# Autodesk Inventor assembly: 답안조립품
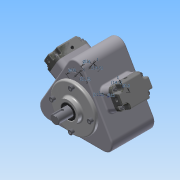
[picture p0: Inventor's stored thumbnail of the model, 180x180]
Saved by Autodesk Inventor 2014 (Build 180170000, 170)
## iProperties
Created: 2015-06
Part Number: 답안조립품
Document SubType Name: Assembly
Designer: Administrator
Mass: 5776.4 g
Surface Area: 2414.93 cm^2
Volume: 1564.62 cm^3
Density: 3.69189 g/cm^3
Author: Administrator
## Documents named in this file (20)
- C:\Documents and Settings\MYHOME\바탕 화면\350605V1053\답안조립품.iam
- C:\Documents and Settings\MYHOME\바탕 화면\350605V1053\본체.ipt
- C:\Documents and Settings\MYHOME\바탕 화면\350605V1053\부시.ipt
- C:\Documents and Settings\MYHOME\바탕 화면\350605V1053\편심축.ipt
- C:\Documents and Settings\MYHOME\바탕 화면\350605V1053\베어링 NA 4904.ipt
- 베어링 NA 4904.ipt
- C:\Documents and Settings\MYHOME\바탕 화면\350605V1053\슬라이드.ipt
- C:\Documents and Settings\MYHOME\바탕 화면\350605V1053\앞커버.ipt
- C:\Documents and Settings\MYHOME\바탕 화면\350605V1053\오일실.ipt
- 오일실.ipt
- C:\Documents and Settings\MYHOME\바탕 화면\350605V1053\헤더커버.ipt
- 헤더커버.ipt
- C:\Documents and Settings\MYHOME\바탕 화면\350605V1053\M6x0.7x20.ipt
- M6x0.7x20.ipt
- C:\Documents and Settings\MYHOME\바탕 화면\350605V1053\M4x0.5x16.ipt
- M4x0.5x16.ipt
- C:\Documents and Settings\MYHOME\바탕 화면\350605V1053\가변스프링2.ipt
- C:\Documents and Settings\MYHOME\바탕 화면\350605V1053\가변1.ipt
- C:\Documents and Settings\MYHOME\바탕 화면\350605V1053\가변스프링4.ipt
- C:\Documents and Settings\MYHOME\바탕 화면\350605V1053\가변스프링3.ipt
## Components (14 placed, 3 different names)
1. 헤더커버:1
2. 헤더커버:2
3. M6x0.7x20:1
4. M6x0.7x20:2
5. M6x0.7x20:3
6. M6x0.7x20:4
7. M4x0.5x16:1
8. M4x0.5x16:2
9. M4x0.5x16:3
10. M4x0.5x16:4
11. M4x0.5x16:5
12. M4x0.5x16:6
13. M4x0.5x16:7
14. M4x0.5x16:8
